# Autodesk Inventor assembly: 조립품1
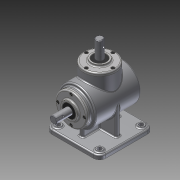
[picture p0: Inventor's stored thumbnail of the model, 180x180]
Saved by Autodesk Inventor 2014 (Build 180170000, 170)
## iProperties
Created: 2015-07
Part Number: 조립품1
Document SubType Name: Assembly
Designer: Owner
Author: Owner
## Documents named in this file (14)
- C:\Documents and Settings\Owner\바탕 화면\450705V1011\조립품1.iam
- C:\Documents and Settings\Owner\바탕 화면\450705V1011\M4.ipt
- C:\Documents and Settings\Owner\바탕 화면\450705V1011\메인 베벨기어.ipt
- C:\Documents and Settings\Owner\바탕 화면\450705V1011\메인 축.ipt
- 메인 축.ipt
- C:\Documents and Settings\Owner\바탕 화면\450705V1011\베어링 6203.ipt
- C:\Documents and Settings\Owner\바탕 화면\450705V1011\본체.ipt
- C:\Documents and Settings\Owner\바탕 화면\450705V1011\서브 베벨기어.ipt
- C:\Documents and Settings\Owner\바탕 화면\450705V1011\서브 축.ipt
- 서브 축.ipt
- C:\Documents and Settings\Owner\바탕 화면\450705V1011\오일실.ipt
- C:\Documents and Settings\Owner\바탕 화면\450705V1011\커버.ipt
- C:\Documents and Settings\Owner\바탕 화면\450705V1011\키 4x4.ipt
- C:\Documents and Settings\Owner\바탕 화면\450705V1011\키 5x5.ipt
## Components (8 placed, 1 different names)
1. M4:2
2. M4:3
3. M4:4
4. M4:5
5. M4:1
6. M4:6
7. M4:7
8. M4:8
